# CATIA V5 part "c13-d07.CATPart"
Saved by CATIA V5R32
Part number: Part1
Bounding box of the stored display mesh (mm): x -49.812 to 35, y -44.222 to 44.222, z 0 to 30
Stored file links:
  D:\PROJECTS\Project 2022\CATIA V5 6R 2022\Resources\Part Files\c13_catia_v5_6r2022_prt\c13_catia_v5-6r2022_figr_13-29\c13-d07.CATPart
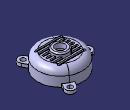
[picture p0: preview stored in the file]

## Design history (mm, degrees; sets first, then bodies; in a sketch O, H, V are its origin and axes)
Body1 (main body)
  Sketch1 on yz-plane, origin (0, 0, 0), H (0, 1, 0), V (0, 0, 1)
    line L1 (0, 0) -> (35, 0)
    line L2 (35, 0) -> (35, 15)
    arc A1 centre (25, 15) radius 10 from (35, 15) to (25, 25) ccw
    line L3 (25, 25) -> (0, 25)
    point P5 (0, 25)
    line L4 (0, 25) -> (0, 0)
    axis line L5 (0, 70.1891) -> (0, -36.6898)
    point P6 (0, 70.1891)
    radius about axis L2 L5 = 35
    distance L1 L3 = 25
    radius A1 = 10
    horizontal: L1 H
    vertical: L2 V, L4 V, L5 V
    tangency: A1 L2, L3 A1
    coincidence: P5 V, P6 V
  Shaft1: profile Sketch1, axis Sketch1.L5, angle 360
  Shell1: ExtOffset 0, Face face of Shaft1, IntOffset 2.5
  Sketch2 on face of Shaft1, origin (0, 0, 0), H (1, 0, 0), V (0, -1, 0)
    projected circle E1 centre (0, 0) radius 35 from edge [face of Shaft1 | face of Shaft1]
    projected arc E2 centre (0, 0) radius 35 from (-34.187, 7.5) to (-34.187, -7.5) ccw from edge [face of Shaft1 | face of Shaft1]
    point P1 (-34.187, 7.5)
    line L1 (-34.187, 7.5) -> (-42.5, 7.5)
    arc A1 centre (-42.5, 0) radius 7.5 from (-42.5, 7.5) to (-42.5, -7.5) ccw
    point P3 (-42.5, 0)
    line L2 (-42.5, -7.5) -> (-34.187, -7.5)
    point P5 (-34.187, -7.5)
    circle A2 centre (-42.5, 0) radius 3.75
    distance P3 V = 42.5
    radius A1 = 7.5
    radius A2 = 3.75
    coincidence: P1 E1, P5 E1, P3 H
    horizontal: L1 H, L2 H
    tangency: A1 L1, L2 A1
  Pad1: profile Sketch2, direction (0, 0, 1), length 5
  CircPattern1: of Pad1, instances 3, angular step 120 {= 360.0*1 deg/CircPattern1.AngularNumber}, axis from face of Shaft1
  Sketch3 on face of Shaft1, origin (0, 0, 25), H (1, 0, 0), V (0, 1, 0)
    construction line L1 (-20, -18) -> (20, -18)
    point P2 (20, -18)
    line L2 (-20, -16.25) -> (20, -16.25)
    line L3 (20, -19.75) -> (-20, -19.75)
    arc A1 centre (20, -18) radius 1.75 from (20, -16.25) to (20, -19.75) cw
    arc A2 centre (-20, -18) radius 1.75 from (-20, -19.75) to (-20, -16.25) cw
    length L1 = 40
    distance H L1 = 18
    distance P2 V = 20
    distance L3 L2 = 3.5
    horizontal: L1 H
    tangency: A1 L2, A2 L2, A1 L3, A2 L3
    parallelism: L1 L2
  Pocket1: profile Sketch3, direction (0, 0, -1), through (limit type 3)
  RectPattern1: of Pocket1, direction 1 instances 7, spacing 6, along yz-plane
  Sketch4 on yz-plane, origin (0, 0, 0), H (0, 1, 0), V (0, 0, 1)
    axis line L1 (0, 0) -> (0, 35.5018)
    point P2 (0, 22.5)
    line L2 (0, 22.5) -> (12.5, 22.5)
    line L3 (12.5, 22.5) -> (12.5, 28)
    arc A1 centre (10.5, 28) radius 2 from (12.5, 28) to (10.5, 30) ccw
    line L4 (10.5, 30) -> (0, 30)
    point P7 (0, 30)
    line L5 (0, 30) -> (0, 22.5)
    reference intersected line E1 (25, 22.5) -> (-25, 22.5) from face of Shell1
    radius about axis L3 L1 = 12.5
    distance L4 L2 = 7.5
    radius A1 = 2
    vertical: L1 V, L3 V, L5 V
    coincidence: P2 L1, P7 L1, L2 E1
    horizontal: L2 H, L4 H
    tangency: A1 L3, L4 A1
  Shaft2: profile Sketch4, axis Sketch4.L1, angle 360
  Sketch5 on face of Shaft2, origin (0, 0, 30), H (1, 0, 0), V (0, 1, 0)
    point P1 (0, 0)
    reference projected circle E1 centre (0, 0) radius 12.5 from edge [face of Shaft2 | face of Shaft2]
    concentricity: P1 E1
  Hole1: placed by Sketch5, at (0, 0, 30) direction (0, 0, -1), diameter 15, through (limit type 3)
